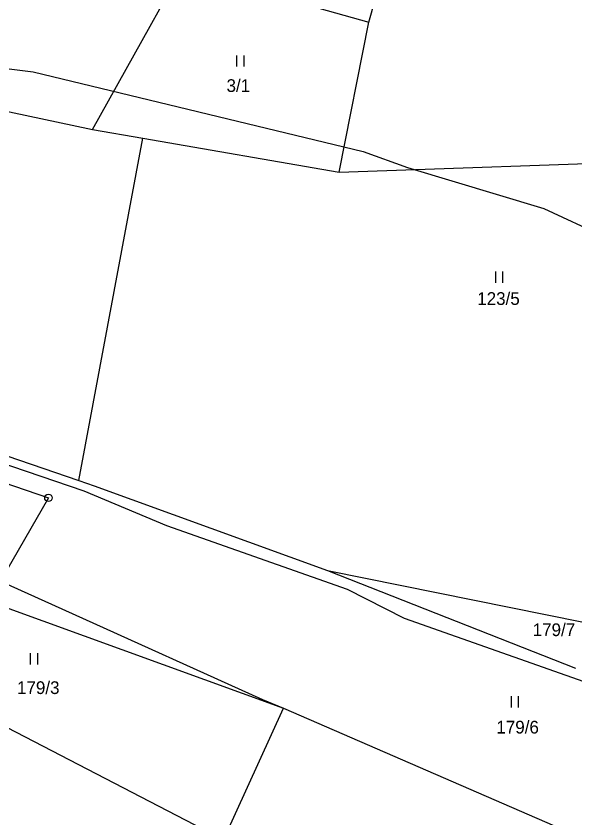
# Model space of a CAD drawing. Extents: x -743888 to -742027, y -1128394 to -1126768.
# Drawn here: x -742818.4 to -742743.6, y -1127432.2 to -1127325 of the extents above; entities that cross this region are included whole.
import ezdxf

# ---------------------------------------------------------------- set-up
doc = ezdxf.new("R2010")
doc.units = 0
for name, color, linetype in [('Vrstva 1', 7, 'Continuous'), ('Vrstva 18', 7, 'Continuous'), ('Vrstva 24', 7, 'Continuous'), ('Vrstva 25', 7, 'Continuous'), ('Vrstva 52', 7, 'Continuous'), ('Vrstva 6', 7, 'Continuous')]:
    doc.layers.add(name, color=color, linetype=linetype)

msp = doc.modelspace()

# ---------------------------------------------------------------- linework, layer by layer
at = {"layer": 'Vrstva 1'}
for points in [[(-742771.16, -1127325.84), (-742768.44, -1127316.21)], [(-742808.12, -1127340.19), (-742796.97, -1127320.16)], [(-742778.95, -1127323.64), (-742771.16, -1127325.84)], [(-742775.15, -1127345.88), (-742771.16, -1127325.84)], [(-742832.48, -1127335.04), (-742808.12, -1127340.19)], [(-742808.12, -1127340.19), (-742801.38, -1127341.35)], [(-742801.38, -1127341.35), (-742775.15, -1127345.88)], [(-742775.15, -1127345.88), (-742731.72, -1127344.4)], [(-742840.33, -1127376.73), (-742809.96, -1127387.12)], [(-742849.91, -1127378.55), (-742841.21, -1127380.13), (-742814.03, -1127389.43), (-742820.42, -1127400.56)], [(-742809.96, -1127387.12), (-742807.93, -1127387.81)], [(-742807.93, -1127387.81), (-742776.69, -1127399.15)], [(-742776.69, -1127399.15), (-742742.44, -1127406.06)], [(-742820.42, -1127400.56), (-742810.86, -1127404.89)], [(-742810.86, -1127404.89), (-742785.4, -1127416.41)], [(-742822, -1127418.91), (-742793.34, -1127433.72)]]:
    msp.add_lwpolyline(points, dxfattribs=at)
at = {"layer": 'Vrstva 24'}
msp.add_line((-742814.08, -1127389.43), (-742813.98, -1127389.43), dxfattribs=at)
msp.add_circle((-742814.03, -1127389.43), 0.499, dxfattribs=at)
at = {"layer": 'Vrstva 25'}
for p, q in [((-742788.85, -1127330.29), (-742788.85, -1127331.79)), ((-742787.85, -1127331.79), (-742787.85, -1127330.29)), ((-742754.23, -1127359.19), (-742754.23, -1127360.69)), ((-742753.23, -1127360.69), (-742753.23, -1127359.19)), ((-742816.45, -1127410.2), (-742816.45, -1127411.7)), ((-742815.45, -1127411.7), (-742815.45, -1127410.2)), ((-742752.14, -1127415.96), (-742752.14, -1127417.46)), ((-742751.14, -1127417.46), (-742751.14, -1127415.96))]:
    msp.add_line(p, q, dxfattribs=at)
at = {"layer": 'Vrstva 52'}
for points in [[(-742848.82, -1127325.8), (-742833.44, -1127329.13), (-742822.88, -1127331.63), (-742816.06, -1127332.5), (-742771.94, -1127343.13), (-742766, -1127345.25), (-742747.75, -1127350.75), (-742739.69, -1127354.5), (-742698.56, -1127368.5), (-742667.56, -1127377.88), (-742637.5, -1127385.5), (-742631.13, -1127387.63), (-742605.63, -1127394), (-742556.88, -1127403.75), (-742548.38, -1127404.63), (-742546.25, -1127405.5), (-742503, -1127408), (-742474.13, -1127407.63), (-742424.94, -1127406.75)], [(-742867.75, -1127371.9), (-742854.96, -1127374.45), (-742854.69, -1127374.5), (-742834.31, -1127380), (-742809.31, -1127388.5), (-742798.25, -1127393.13), (-742774.06, -1127401.63), (-742766.44, -1127405.5), (-742723.19, -1127420.75), (-742707.88, -1127427.13), (-742679.5, -1127436.38), (-742644.69, -1127444.5), (-742572.13, -1127460.13), (-742533.94, -1127463.63), (-742511.88, -1127465.75), (-742505.56, -1127465.75), (-742489.44, -1127467.75), (-742456.75, -1127469.5), (-742444.44, -1127470.75)]]:
    msp.add_lwpolyline(points, dxfattribs=at)
at = {"layer": 'Vrstva 6'}
for points in [[(-742809.96, -1127387.12), (-742801.38, -1127341.35)], [(-742776.69, -1127399.15), (-742743.5, -1127412.2)], [(-742830.94, -1127400.02), (-742782.56, -1127417.54)], [(-742785.4, -1127416.41), (-742782.56, -1127417.54)], [(-742790.61, -1127435.15), (-742782.56, -1127417.54)], [(-742782.56, -1127417.54), (-742741.92, -1127435.21)]]:
    msp.add_lwpolyline(points, dxfattribs=at)

# ---------------------------------------------------------------- texts
at = {"layer": 'Vrstva 18'}
for s, p in [('3/1', (-742790.2, -1127335.17)), ('123/5', (-742756.66, -1127363.64)), ('179/7', (-742749.24, -1127407.92)), ('179/3', (-742818.23, -1127415.66)), ('179/6', (-742754.1, -1127420.94))]:
    msp.add_text(s, height=1.7, dxfattribs=at).set_placement(p)

doc.saveas('drawing.dxf')
